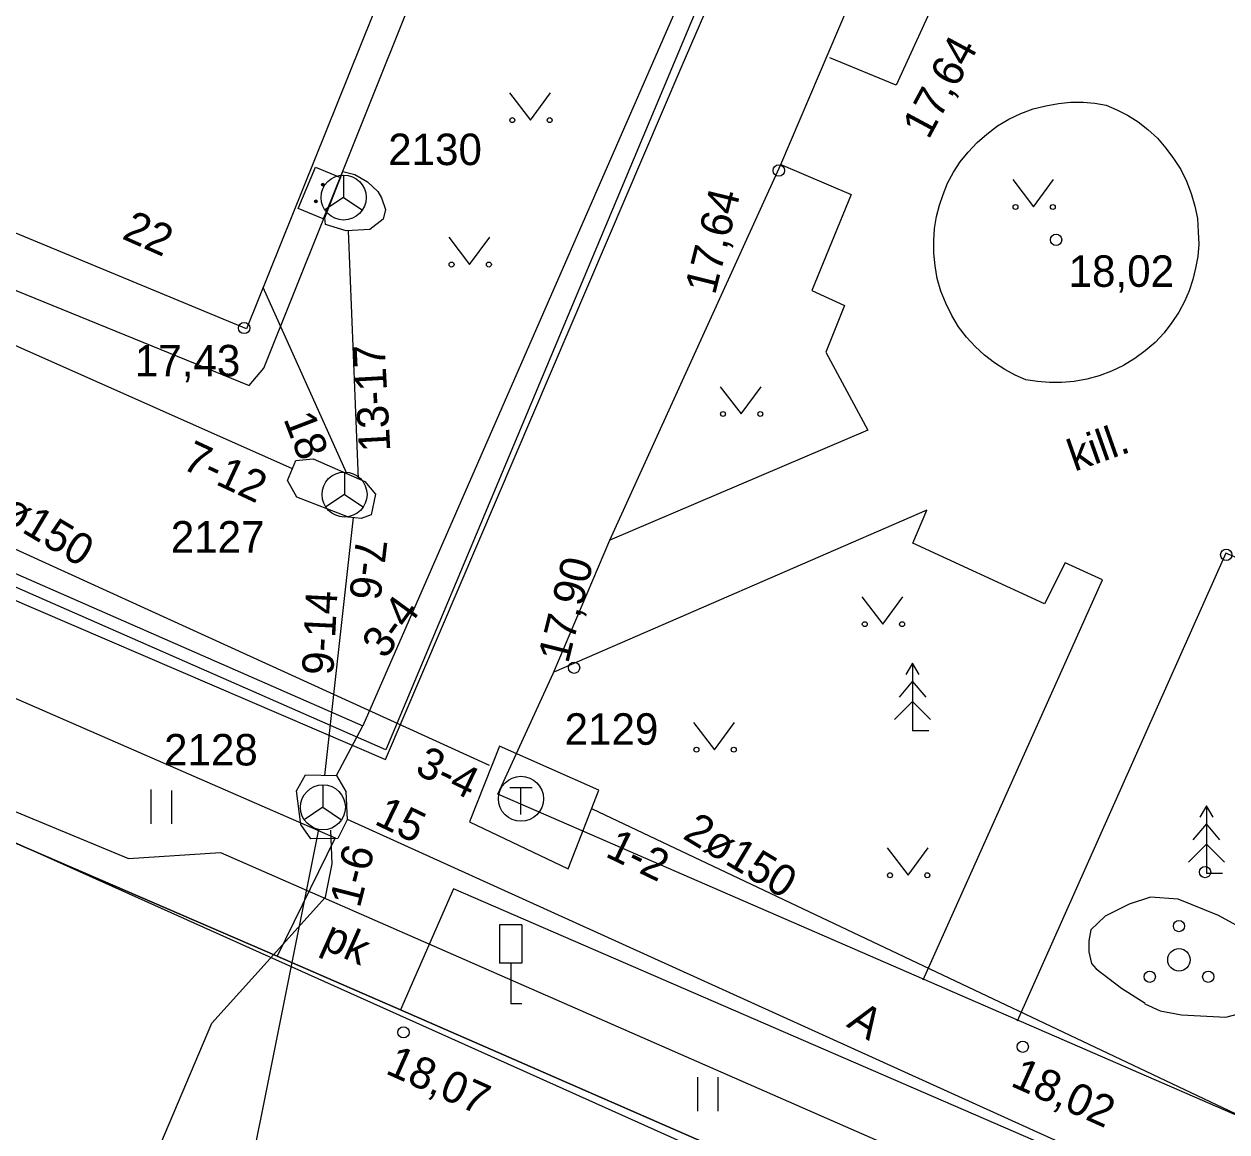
# Model space of a CAD drawing. Extents: x 713497 to 713863, y 6590062 to 6590327.
# Drawn here: x 713569.52 to 713596.25, y 6590260.04 to 6590284.65 of the extents above; entities that cross this region are included whole.
import ezdxf

# ---------------------------------------------------------------- set-up
doc = ezdxf.new("R2010")
doc.units = 0
for name, color, linetype in [('HALJASTUS', 7, 'Continuous'), ('HOONE', 7, 'Continuous'), ('HOONEDET', 7, 'Continuous'), ('KORGUS', 7, 'Continuous'), ('KPKAABEL', 7, 'Continuous'), ('KTRASS', 7, 'Continuous'), ('LIIKLUS', 7, 'Continuous'), ('POST', 7, 'Continuous'), ('PUU', 7, 'Continuous'), ('SIKAEV', 7, 'Continuous'), ('SITRASS', 7, 'Continuous'), ('TEE', 7, 'Continuous'), ('TKAEV', 7, 'Continuous'), ('TORU NR', 7, 'Continuous'), ('TTRASS', 7, 'Continuous'), ('Слой 1', 7, 'Continuous')]:
    doc.layers.add(name, color=color, linetype=linetype)

msp = doc.modelspace()

# ---------------------------------------------------------------- linework, layer by layer
at = {"layer": 'HALJASTUS'}
for p, q in [((713580.307, 6590283.127), (713580.77, 6590282.52)), ((713580.77, 6590282.52), (713581.216, 6590283.127)), ((713591.487, 6590281.197), (713591.95, 6590280.59)), ((713591.95, 6590280.59), (713592.396, 6590281.197)), ((713578.957, 6590279.917), (713579.42, 6590279.31)), ((713579.42, 6590279.31), (713579.866, 6590279.917)), ((713584.987, 6590276.597), (713585.45, 6590275.99)), ((713585.45, 6590275.99), (713585.896, 6590276.597)), ((713588.137, 6590271.927), (713588.6, 6590271.32)), ((713588.6, 6590271.32), (713589.046, 6590271.927)), ((713584.397, 6590269.137), (713584.86, 6590268.53)), ((713584.86, 6590268.53), (713585.306, 6590269.137)), ((713572.337, 6590267.646), (713572.337, 6590266.885)), ((713572.792, 6590267.624), (713572.792, 6590266.885)), ((713588.697, 6590266.347), (713589.16, 6590265.74)), ((713589.16, 6590265.74), (713589.606, 6590266.347)), ((713584.483, 6590261.257), (713584.483, 6590260.496)), ((713584.938, 6590261.257), (713584.938, 6590260.496))]:
    msp.add_line(p, q, dxfattribs=at)
msp.add_lwpolyline([(713594.42, 6590262.88), (713594.76, 6590262.73), (713595.24, 6590262.64), (713595.8, 6590262.61), (713596.22, 6590262.59), (713596.53, 6590262.67), (713596.84, 6590263), (713597.04, 6590263.6), (713597.01, 6590264.11), (713596.76, 6590264.46), (713596.06, 6590264.85), (713595.16, 6590265.21), (713594.55, 6590265.25), (713594.07, 6590265.1), (713593.54, 6590264.83), (713593.22, 6590264.53), (713593.18, 6590264.28), (713593.18, 6590264.04), (713593.24, 6590263.78), (713593.34, 6590263.66), (713593.9, 6590263.23), (713594.43, 6590262.9)], dxfattribs=at)
for centre, radius in [((713580.369, 6590282.52), 0.055), ((713581.198, 6590282.52), 0.055), ((713591.549, 6590280.59), 0.055), ((713592.378, 6590280.59), 0.055), ((713579.019, 6590279.31), 0.055), ((713579.848, 6590279.31), 0.055), ((713585.049, 6590275.99), 0.055), ((713585.878, 6590275.99), 0.055), ((713588.199, 6590271.32), 0.055), ((713589.028, 6590271.32), 0.055), ((713584.459, 6590268.53), 0.055), ((713585.288, 6590268.53), 0.055), ((713588.759, 6590265.74), 0.055), ((713589.588, 6590265.74), 0.055), ((713595.18, 6590264.61), 0.125), ((713595.18, 6590263.86), 0.25), ((713594.53, 6590263.485), 0.125), ((713595.83, 6590263.485), 0.125)]:
    msp.add_circle(centre, radius, dxfattribs=at)
at = {"layer": 'HOONE'}
for points in [[(713576.17, 6590314.75), (713587.41, 6590310.13), (713584.84, 6590303.68), (713574.46, 6590277.88), (713561.56, 6590283.23), (713540.52, 6590292.12), (713545.44, 6590303.77), (713562.22, 6590296.81), (713560.95, 6590293.78), (713566.64, 6590291.4), (713576.17, 6590314.75)], [(713527.261, 6590284.603), (713571.838, 6590266.115), (713573.888, 6590266.247), (713614.395, 6590248.483), (713630.517, 6590241.151), (713667.174, 6590224.027), (713666.91, 6590213.67), (713710.13, 6590192.26), (713734.713, 6590179.152)]]:
    msp.add_lwpolyline(points, dxfattribs=at)
at = {"layer": 'HOONEDET'}
msp.add_lwpolyline([(713552.8, 6590301.69), (713544.9, 6590305.16), (713544.79, 6590305.11), (713544.58, 6590304.93), (713543.52, 6590302.01), (713542.37, 6590299.46), (713539.43, 6590291.91), (713539.49, 6590291.52), (713543.9, 6590289.7), (713547.82, 6590287.88), (713558.4, 6590283.41), (713566.79, 6590279.77), (713574.52, 6590276.62), (713574.85, 6590277.01), (713576.84, 6590281.98), (713578.43, 6590285.96)], dxfattribs=at)
at = {"layer": 'KORGUS'}
for centre in [(713586.29, 6590281.4), (713592.45, 6590279.86), (713574.41, 6590277.9), (713596.23, 6590272.86), (713581.74, 6590270.35), (713595.76, 6590265.81), (713577.95, 6590262.25), (713591.71, 6590261.93)]:
    msp.add_circle(centre, 0.125, dxfattribs=at)
at = {"layer": 'KPKAABEL'}
msp.add_lwpolyline([(713529.988, 6590287.362), (713528.13, 6590283.39), (713562.908, 6590269.342), (713609.57, 6590248.393), (713642.834, 6590233.164), (713665.543, 6590222.669), (713703.801, 6590203.145), (713710.007, 6590200.019), (713735.256, 6590187.298), (713757.247, 6590176.218), (713786.95, 6590160.25), (713778.485, 6590144.103)], dxfattribs=at)
at = {"layer": 'KTRASS'}
msp.add_lwpolyline([(713576.46, 6590267.96), (713577.05, 6590269.06)], dxfattribs=at)
at = {"layer": 'LIIKLUS'}
for points in [[(713580.083, 6590264.636), (713580.083, 6590263.786)], [(713580.583, 6590264.636), (713580.083, 6590264.636)], [(713580.583, 6590264.636), (713580.583, 6590263.786)], [(713580.583, 6590263.786), (713580.083, 6590263.786)], [(713580.333, 6590263.786), (713580.333, 6590262.886)], [(713580.583, 6590262.886), (713580.333, 6590262.886)]]:
    msp.add_lwpolyline(points, dxfattribs=at)
at = {"layer": 'POST'}
msp.add_lwpolyline([(713575.611, 6590280.553), (713575.995, 6590281.477), (713576.549, 6590281.247), (713576.165, 6590280.323)], close=True, dxfattribs=at)
for centre, radius in [((713576.157, 6590281.085), 0.0304), ((713576.157, 6590281.085), 0.029), ((713576.157, 6590281.085), 0.0277), ((713576.157, 6590281.085), 0.0263), ((713576.157, 6590281.085), 0.0249), ((713576.157, 6590281.085), 0.0236), ((713576.157, 6590281.085), 0.0222), ((713576.157, 6590281.085), 0.0209), ((713576.157, 6590281.085), 0.0195), ((713576.157, 6590281.085), 0.0181), ((713576.157, 6590281.085), 0.0168), ((713576.157, 6590281.085), 0.0154), ((713576.157, 6590281.085), 0.014), ((713576.157, 6590281.085), 0.0127), ((713576.157, 6590281.085), 0.0113), ((713576.157, 6590281.085), 0.00996), ((713576.157, 6590281.085), 0.0086), ((713576.157, 6590281.085), 0.00724), ((713576.157, 6590281.085), 0.00587), ((713576.157, 6590281.085), 0.00451), ((713576.157, 6590281.085), 0.00315), ((713576.157, 6590281.085), 0.00179), ((713576.157, 6590281.085), 0.000426), ((713576.003, 6590280.715), 0.0304), ((713576.003, 6590280.715), 0.029), ((713576.003, 6590280.715), 0.0277), ((713576.003, 6590280.715), 0.0263), ((713576.003, 6590280.715), 0.0249), ((713576.003, 6590280.715), 0.0236), ((713576.003, 6590280.715), 0.0222), ((713576.003, 6590280.715), 0.0209), ((713576.003, 6590280.715), 0.0195), ((713576.003, 6590280.715), 0.0181), ((713576.003, 6590280.715), 0.0168), ((713576.003, 6590280.715), 0.0154), ((713576.003, 6590280.715), 0.014), ((713576.003, 6590280.715), 0.0127), ((713576.003, 6590280.715), 0.0113), ((713576.003, 6590280.715), 0.00996), ((713576.003, 6590280.715), 0.0086), ((713576.003, 6590280.715), 0.00724), ((713576.003, 6590280.715), 0.00587), ((713576.003, 6590280.715), 0.00451), ((713576.003, 6590280.715), 0.00315), ((713576.003, 6590280.715), 0.00179), ((713576.003, 6590280.715), 0.000426)]:
    msp.add_circle(centre, radius, dxfattribs=at)
at = {"layer": 'PUU'}
for p, q in [((713589.26, 6590270.45), (713589.11, 6590270.2)), ((713589.41, 6590270.2), (713589.26, 6590270.45)), ((713589.26, 6590270.45), (713589.26, 6590268.95)), ((713589.26, 6590270.05), (713588.96, 6590269.7)), ((713589.56, 6590269.7), (713589.26, 6590270.05)), ((713589.26, 6590269.6), (713588.86, 6590269.2)), ((713589.66, 6590269.2), (713589.26, 6590269.6)), ((713589.62, 6590268.95), (713589.26, 6590268.95)), ((713595.79, 6590267.28), (713595.64, 6590267.03)), ((713595.94, 6590267.03), (713595.79, 6590267.28)), ((713595.79, 6590267.28), (713595.79, 6590265.78)), ((713595.79, 6590266.88), (713595.49, 6590266.53)), ((713596.09, 6590266.53), (713595.79, 6590266.88)), ((713595.79, 6590266.43), (713595.39, 6590266.03)), ((713596.19, 6590266.03), (713595.79, 6590266.43)), ((713596.15, 6590265.78), (713595.79, 6590265.78))]:
    msp.add_line(p, q, dxfattribs=at)
at = {"layer": 'SIKAEV'}
for p, q in [((713576.62, 6590281.3), (713576.62, 6590280.8)), ((713576.62, 6590280.8), (713576.205, 6590280.525)), ((713576.62, 6590280.8), (713577.035, 6590280.525)), ((713576.64, 6590274.7), (713576.64, 6590274.2)), ((713576.64, 6590274.2), (713576.225, 6590273.925)), ((713576.64, 6590274.2), (713577.055, 6590273.925)), ((713576.16, 6590267.75), (713576.16, 6590267.25)), ((713576.16, 6590267.25), (713575.745, 6590266.975)), ((713576.16, 6590267.25), (713576.575, 6590266.975))]:
    msp.add_line(p, q, dxfattribs=at)
for centre in [(713576.62, 6590280.8), (713576.64, 6590274.2), (713576.16, 6590267.25)]:
    msp.add_circle(centre, 0.5, dxfattribs=at)
at = {"layer": 'SITRASS'}
for points in [[(713496.861, 6590307.708), (713502.281, 6590305.611), (713510.011, 6590302.954), (713510.942, 6590302.591), (713521.663, 6590298.107), (713527.894, 6590295.506), (713527.931, 6590295.59), (713554.1, 6590284.28), (713575.48, 6590274.78)], [(713496.861, 6590303.284), (713500.921, 6590301.592), (713518.63, 6590294.21), (713525.943, 6590291.121), (713547.87, 6590281.86), (713577.05, 6590269.06)], [(713590.38, 6590299.57), (713577.05, 6590269.06)], [(713576.6, 6590281.38), (713576.87, 6590281.31), (713577.15, 6590281.15), (713577.38, 6590280.93), (713577.46, 6590280.79), (713577.55, 6590280.53), (713577.5, 6590280.32), (713577.2, 6590280.09), (713576.68, 6590280.06), (713576.22, 6590280.2), (713576.2, 6590280.35), (713576.6, 6590281.38)], [(713576.95, 6590274.55), (713576.73, 6590280.06)], [(713576.69, 6590274.67), (713574.83, 6590278.8)], [(713575.94, 6590274.99), (713577.09, 6590274.49), (713577.33, 6590274.21), (713577.23, 6590273.75), (713577.01, 6590273.67), (713576.73, 6590273.7), (713575.58, 6590274.14), (713575.37, 6590274.51), (713575.56, 6590274.96), (713575.94, 6590274.99)], [(713576.2, 6590267.96), (713576.84, 6590273.69)], [(713576.46, 6590267.96), (713576.67, 6590267.6), (713576.7, 6590266.97), (713576.49, 6590266.56), (713575.89, 6590266.55), (713575.67, 6590266.87), (713575.57, 6590267.62), (713575.77, 6590267.97), (713576.46, 6590267.96)], [(713576.7, 6590266.99), (713616.543, 6590248.92)], [(713566.805, 6590246.216), (713573.691, 6590262.451), (713576.214, 6590265.257), (713576.368, 6590265.991), (713576.338, 6590266.741)], [(713576.062, 6590266.76), (713572.56, 6590249.272)]]:
    msp.add_lwpolyline(points, dxfattribs=at)
at = {"layer": 'TEE'}
for points in [[(713670.756, 6590228.07), (713634.678, 6590243.788), (713580.049, 6590267.542), (713581.278, 6590270.224), (713582.538, 6590273.183), (713586.336, 6590281.535), (713592.563, 6590296.145)], [(713592.563, 6590296.145), (713601.93, 6590291.83), (713599.012, 6590284.7), (713598.07, 6590285.149), (713598.387, 6590285.961), (713595.29, 6590287.098), (713594.96, 6590286.133), (713594.048, 6590286.449), (713592.574, 6590286.177), (713591.001, 6590285.886), (713590.549, 6590284.92), (713589.797, 6590285.271), (713588.899, 6590283.294), (713587.424, 6590283.905)], [(713534.555, 6590288.23), (713532.071, 6590289.283), (713530.856, 6590286.52), (713538.894, 6590282.951), (713576.43, 6590266.575), (713575.141, 6590263.944)], [(713531.546, 6590288.09), (713554.39, 6590278.27), (713577.55, 6590268.31), (713584.12, 6590283.68), (713584.86, 6590285.4), (713583.07, 6590286.2), (713581.2, 6590286.96)], [(713593.56, 6590282.85), (713593.8, 6590282.75), (713594.04, 6590282.63), (713594.27, 6590282.48), (713594.49, 6590282.31), (713594.7, 6590282.12), (713594.89, 6590281.9), (713595.06, 6590281.67), (713595.22, 6590281.42), (713595.35, 6590281.16), (713595.45, 6590280.89), (713595.53, 6590280.61), (713595.59, 6590280.33), (713595.61, 6590280.04), (713595.62, 6590279.76), (713595.6, 6590279.49), (713595.55, 6590279.23), (713595.49, 6590278.98), (713595.41, 6590278.73), (713595.3, 6590278.49), (713595.18, 6590278.25), (713595.02, 6590278.02), (713594.85, 6590277.79), (713594.65, 6590277.58), (713594.43, 6590277.39), (713594.2, 6590277.22), (713593.95, 6590277.07), (713593.68, 6590276.94), (713593.41, 6590276.84), (713593.13, 6590276.76), (713592.85, 6590276.71), (713592.57, 6590276.69), (713592.3, 6590276.69), (713592.04, 6590276.71), (713591.78, 6590276.75), (713591.54, 6590276.85), (713591.31, 6590276.98), (713591.08, 6590277.13), (713590.86, 6590277.3), (713590.65, 6590277.49), (713590.46, 6590277.7), (713590.28, 6590277.93), (713590.13, 6590278.18), (713590, 6590278.45), (713589.89, 6590278.72), (713589.81, 6590279), (713589.76, 6590279.28), (713589.73, 6590279.56), (713589.73, 6590279.84), (713589.75, 6590280.11), (713589.79, 6590280.38), (713589.86, 6590280.63), (713589.94, 6590280.87), (713590.04, 6590281.12), (713590.17, 6590281.36), (713590.32, 6590281.59), (713590.5, 6590281.81), (713590.7, 6590282.02), (713590.91, 6590282.21), (713591.15, 6590282.39), (713591.4, 6590282.54), (713591.67, 6590282.67), (713591.94, 6590282.77), (713592.22, 6590282.84), (713592.5, 6590282.89), (713592.77, 6590282.92), (713593.05, 6590282.92), (713593.31, 6590282.9), (713593.56, 6590282.85)], [(713666.108, 6590223.285), (713665.125, 6590223.708), (713665.399, 6590224.292), (713664.368, 6590224.758), (713664.105, 6590224.17), (713638.24, 6590236.433), (713616.511, 6590245.926), (713594.802, 6590255.36), (713577.886, 6590262.747), (713575.141, 6590263.944), (713556.827, 6590271.855), (713531.631, 6590282.846), (713531.578, 6590282.869)], [(713531.578, 6590282.869), (713531.631, 6590282.846), (713556.827, 6590271.855), (713575.141, 6590263.944), (713577.886, 6590262.747), (713594.802, 6590255.36), (713616.511, 6590245.926), (713638.24, 6590236.433), (713664.105, 6590224.17), (713664.368, 6590224.758), (713665.399, 6590224.292), (713665.125, 6590223.708), (713666.108, 6590223.285), (713666.434, 6590223.151), (713669.603, 6590225.318), (713669.834, 6590225.893), (713641.724, 6590238.195), (713621.946, 6590246.858), (713579.058, 6590265.436), (713577.886, 6590262.747)], [(713593.56, 6590282.85), (713593.56, 6590282.85)], [(713586.336, 6590281.535), (713587.899, 6590280.866), (713587.021, 6590278.733), (713587.752, 6590278.402), (713587.337, 6590277.36), (713588.27, 6590275.631), (713582.538, 6590273.183)], [(713589.495, 6590263.415), (713593.484, 6590272.302), (713592.651, 6590272.684), (713592.194, 6590271.769), (713589.264, 6590273.118), (713589.578, 6590273.854), (713581.291, 6590270.252)], [(713631.759, 6590245.03), (713630.049, 6590254.438), (713617.269, 6590259.855), (713618.646, 6590263.406), (713596.22, 6590272.9), (713591.585, 6590262.502)]]:
    msp.add_lwpolyline(points, dxfattribs=at)
at = {"layer": 'TKAEV'}
for p, q in [((713580.31, 6590267.69), (713580.81, 6590267.69)), ((713580.56, 6590267.09), (713580.56, 6590267.69))]:
    msp.add_line(p, q, dxfattribs=at)
msp.add_circle((713580.56, 6590267.44), 0.5, dxfattribs=at)
at = {"layer": 'TTRASS'}
for points in [[(713579.86, 6590268.18), (713569.16, 6590273.06), (713552.4, 6590280.47), (713525.759, 6590292.472)], [(713580.08, 6590268.61), (713579.42, 6590266.93), (713581.61, 6590265.88), (713582.29, 6590267.63), (713580.08, 6590268.61)], [(713582.143, 6590267.213), (713612.417, 6590252.868), (713616.413, 6590250.919), (713630.042, 6590244.273), (713670.551, 6590224.518), (713678.954, 6590220.421)]]:
    msp.add_lwpolyline(points, dxfattribs=at)
at = {"layer": 'Слой 1'}
msp.add_lwpolyline([(713534.6, 6590307.05), (713570.51, 6590314.26), (713572.89, 6590321.37), (713595.83, 6590312.09), (713577.56, 6590268.53), (713526.91, 6590290.79)], close=True, dxfattribs=at)

# ---------------------------------------------------------------- texts
at = {"layer": 'HOONE'}
msp.add_text('22', height=0.7, rotation=336.1452, dxfattribs=at).set_placement((713571.67, 6590279.896))
at = {"layer": 'KORGUS'}
for s, rotation, p in [('17,64', 61.7067, (713589.616, 6590282.068)), ('17,64', 75.9983, (713584.871, 6590278.616)), ('17,90', 75.9983, (713581.608, 6590270.427)), ('18,07', 335.9107, (713577.524, 6590261.347)), ('18,02', 335.9107, (713591.412, 6590261.071))]:
    msp.add_text(s, height=0.7, rotation=rotation, dxfattribs=at).set_placement(p)
for s, p in [('18,02', (713592.728, 6590278.815)), ('17,43', (713571.981, 6590276.825))]:
    msp.add_text(s, height=0.7, dxfattribs=at).set_placement(p)
at = {"layer": 'SIKAEV'}
for s, p in [('2130', (713577.61, 6590281.52)), ('2127', (713572.78, 6590272.91)), ('2129', (713581.53, 6590268.64)), ('2128', (713572.63, 6590268.18))]:
    msp.add_text(s, height=0.7, dxfattribs=at).set_placement(p)
at = {"layer": 'TEE'}
for s, rotation, p in [('kill.', 19.4508, (713592.859, 6590274.706)), ('pk', 335.8904, (713576.098, 6590264.132)), ('A', 327.1011, (713587.772, 6590262.393))]:
    msp.add_text(s, height=0.7, rotation=rotation, dxfattribs=at).set_placement(p)
at = {"layer": 'TORU NR'}
for s, rotation, p in [('13-17', 93.1121, (713577.659, 6590275.165)), ('18', 290.961, (713575.276, 6590275.884)), ('7-12', 334.9711, (713572.998, 6590274.79)), ('2ø150', 328.9855, (713568.509, 6590273.943)), ('7-6', 263.2939, (713576.9, 6590273.252)), ('9-14', 87.1328, (713576.39, 6590270.175)), ('3-4', 53.8651, (713577.541, 6590270.521)), ('3-4', 334.1942, (713578.177, 6590268.01)), ('15', 334.1942, (713577.277, 6590266.89)), ('2ø150', 328.9855, (713584.129, 6590266.573)), ('1-2', 334.1942, (713582.407, 6590266.17)), ('1-6', 75.5869, (713576.977, 6590264.995))]:
    msp.add_text(s, height=0.7, rotation=rotation, dxfattribs=at).set_placement(p)

doc.saveas('drawing.dxf')
